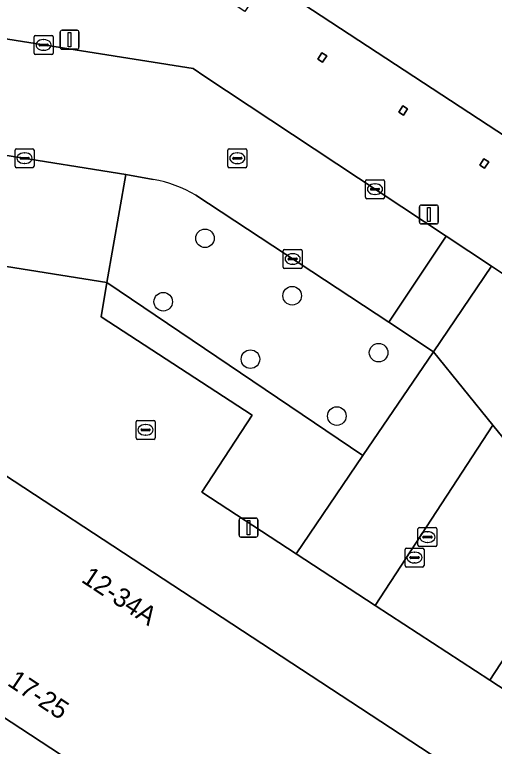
# Model space of a CAD drawing. Extents: x 159279 to 160377, y 384531 to 385888.
# Drawn here: x 159737.29 to 159762.57, y 385027.61 to 385066.14 of the extents above; entities that cross this region are included whole.
import ezdxf

# ---------------------------------------------------------------- set-up
doc = ezdxf.new("R2010")
doc.units = 0
for name, color, linetype in [('IMGEO_Boom', 7, 'Continuous'), ('IMGEO_Groenvoorziening', 7, 'Continuous'), ('IMGEO_Kolk', 7, 'Continuous'), ('IMGEO_Lichtmast', 7, 'Continuous'), ('IMGEO_Pand', 7, 'Continuous'), ('IMGEO_Pand_nummerreeks', 7, 'Continuous'), ('IMGEO_Parkeervlak_open', 7, 'Continuous'), ('IMGEO_Rijbaan_lokaal_open', 7, 'Continuous'), ('IMGEO_Rioolput', 7, 'Continuous'), ('IMGEO_Voetpad_open', 7, 'Continuous')]:
    doc.layers.add(name, color=color, linetype=linetype)

msp = doc.modelspace()

# ---------------------------------------------------------------- linework, layer by layer
at = {"layer": 'IMGEO_Boom'}
for centre in [(159747.32, 385054.365), (159751.915, 385051.341), (159745.121, 385051.024), (159756.467, 385048.344), (159749.716, 385048), (159754.268, 385045.003)]:
    msp.add_circle(centre, 0.489, dxfattribs=at)
at = {"layer": 'IMGEO_Groenvoorziening'}
msp.add_lwpolyline([(159744.597, 385057.462), (159743.153, 385057.729), (159742.143, 385052.029), (159755.642, 385042.921), (159759.353, 385048.383), (159757.004, 385049.945), (159746.836, 385056.637)], dxfattribs=at)
msp.add_lwpolyline([(159752.129, 385037.751), (159755.642, 385042.921), (159742.143, 385052.029), (159741.848, 385050.232), (159749.805, 385045.051), (159747.158, 385040.997)], close=True, dxfattribs=at)
msp.add_arc((159743.481, 385050.982), 6.575, 59.3189, 80.2266, dxfattribs=at)
at = {"layer": 'IMGEO_Kolk'}
for p, q in [((159738.319, 385064.12), (159738.319, 385064.972)), ((159738.394, 385065.046), (159739.246, 385065.046)), ((159738.807, 385064.826), (159738.832, 385064.826)), ((159739.32, 385064.972), (159739.32, 385064.12)), ((159738.578, 385064.54), (159738.578, 385064.552)), ((159739.016, 385064.503), (159738.618, 385064.503)), ((159738.621, 385064.589), (159739.019, 385064.589)), ((159739.062, 385064.552), (159739.062, 385064.54)), ((159739.246, 385064.046), (159738.394, 385064.046)), ((159738.83, 385064.266), (159738.805, 385064.266)), ((159737.316, 385058.157), (159737.316, 385059.009)), ((159737.391, 385059.083), (159738.243, 385059.083)), ((159738.317, 385059.009), (159738.317, 385058.157)), ((159737.618, 385058.626), (159738.016, 385058.626)), ((159737.804, 385058.863), (159737.829, 385058.863)), ((159737.575, 385058.577), (159737.575, 385058.589)), ((159738.013, 385058.54), (159737.615, 385058.54)), ((159737.827, 385058.303), (159737.802, 385058.303)), ((159738.059, 385058.589), (159738.059, 385058.577)), ((159738.243, 385058.083), (159737.391, 385058.083)), ((159755.777, 385056.525), (159755.777, 385057.377)), ((159755.852, 385057.451), (159756.704, 385057.451)), ((159756.265, 385057.231), (159756.29, 385057.231)), ((159756.778, 385057.377), (159756.778, 385056.525)), ((159756.036, 385056.945), (159756.036, 385056.957)), ((159756.474, 385056.908), (159756.076, 385056.908)), ((159756.079, 385056.994), (159756.477, 385056.994)), ((159756.52, 385056.957), (159756.52, 385056.945)), ((159756.704, 385056.451), (159755.852, 385056.451)), ((159756.288, 385056.671), (159756.263, 385056.671)), ((159751.439, 385052.85), (159751.439, 385053.702)), ((159751.514, 385053.776), (159752.366, 385053.776)), ((159752.44, 385053.702), (159752.44, 385052.85)), ((159751.698, 385053.27), (159751.698, 385053.282)), ((159752.136, 385053.233), (159751.738, 385053.233)), ((159751.741, 385053.319), (159752.139, 385053.319)), ((159751.927, 385053.556), (159751.952, 385053.556)), ((159752.182, 385053.282), (159752.182, 385053.27)), ((159751.95, 385052.996), (159751.925, 385052.996)), ((159752.366, 385052.776), (159751.514, 385052.776)), ((159743.766, 385044.778), (159744.618, 385044.778)), ((159743.691, 385043.852), (159743.691, 385044.704)), ((159744.179, 385044.558), (159744.204, 385044.558)), ((159744.692, 385044.704), (159744.692, 385043.852)), ((159743.95, 385044.272), (159743.95, 385044.284)), ((159744.388, 385044.235), (159743.99, 385044.235)), ((159743.993, 385044.321), (159744.391, 385044.321)), ((159744.202, 385043.998), (159744.177, 385043.998)), ((159744.434, 385044.284), (159744.434, 385044.272)), ((159744.618, 385043.778), (159743.766, 385043.778)), ((159758.539, 385038.206), (159758.539, 385039.058)), ((159758.614, 385039.132), (159759.466, 385039.132)), ((159759.54, 385039.058), (159759.54, 385038.206)), ((159758.798, 385038.626), (159758.798, 385038.638)), ((159759.236, 385038.589), (159758.838, 385038.589)), ((159758.841, 385038.675), (159759.239, 385038.675)), ((159759.027, 385038.912), (159759.052, 385038.912)), ((159759.282, 385038.638), (159759.282, 385038.626)), ((159759.05, 385038.352), (159759.025, 385038.352)), ((159759.466, 385038.132), (159758.614, 385038.132))]:
    msp.add_line(p, q, dxfattribs=at)
for points in [[(159738.319, 385064.12), (159738.319, 385064.972)], [(159738.394, 385065.046), (159739.246, 385065.046)], [(159739.32, 385064.972), (159739.32, 385064.12)], [(159739.246, 385064.046), (159738.394, 385064.046)], [(159737.316, 385058.157), (159737.316, 385059.009)], [(159737.391, 385059.083), (159738.243, 385059.083)], [(159738.317, 385059.009), (159738.317, 385058.157)], [(159738.243, 385058.083), (159737.391, 385058.083)], [(159755.777, 385056.525), (159755.777, 385057.377)], [(159755.852, 385057.451), (159756.704, 385057.451)], [(159756.778, 385057.377), (159756.778, 385056.525)], [(159756.704, 385056.451), (159755.852, 385056.451)], [(159751.439, 385052.85), (159751.439, 385053.702)], [(159751.514, 385053.776), (159752.366, 385053.776)], [(159752.44, 385053.702), (159752.44, 385052.85)], [(159752.366, 385052.776), (159751.514, 385052.776)], [(159743.766, 385044.778), (159744.618, 385044.778)], [(159743.691, 385043.852), (159743.691, 385044.704)], [(159744.692, 385044.704), (159744.692, 385043.852)], [(159744.618, 385043.778), (159743.766, 385043.778)], [(159758.539, 385038.206), (159758.539, 385039.058)], [(159758.614, 385039.132), (159759.466, 385039.132)], [(159759.54, 385039.058), (159759.54, 385038.206)], [(159759.466, 385038.132), (159758.614, 385038.132)]]:
    msp.add_lwpolyline(points, dxfattribs=at)
for centre, radius, start, end in [((159738.396, 385064.97), 0.0765, 91.552, 178.448), ((159738.396, 385064.97), 0.0765, 91.552, 178.448), ((159739.244, 385064.97), 0.0765, 1.552, 88.448), ((159739.244, 385064.97), 0.0765, 1.552, 88.448), ((159738.618, 385064.549), 0.0403, 85.8775, 175.7526), ((159738.615, 385064.539), 0.0366, 178.938, 274.7102), ((159739.019, 385064.546), 0.043, 264.8664, 352.4533), ((159739.023, 385064.551), 0.0386, 1.7309, 96.639), ((159738.396, 385064.122), 0.0765, 181.552, 268.448), ((159738.396, 385064.122), 0.0765, 181.552, 268.448), ((159739.244, 385064.122), 0.0765, 271.552, 358.448), ((159739.244, 385064.122), 0.0765, 271.552, 358.448), ((159737.393, 385059.007), 0.0765, 91.552, 178.448), ((159737.393, 385059.007), 0.0765, 91.552, 178.448), ((159738.241, 385059.007), 0.0765, 1.552, 88.448), ((159738.241, 385059.007), 0.0765, 1.552, 88.448), ((159737.615, 385058.586), 0.0403, 85.8775, 175.7526), ((159738.02, 385058.588), 0.0386, 1.7309, 96.639), ((159737.612, 385058.576), 0.0366, 178.938, 274.7102), ((159738.016, 385058.583), 0.043, 264.8664, 352.4533), ((159737.393, 385058.159), 0.0765, 181.552, 268.448), ((159737.393, 385058.159), 0.0765, 181.552, 268.448), ((159738.241, 385058.159), 0.0765, 271.552, 358.448), ((159738.241, 385058.159), 0.0765, 271.552, 358.448), ((159755.854, 385057.375), 0.0765, 91.552, 178.448), ((159755.854, 385057.375), 0.0765, 91.552, 178.448), ((159756.702, 385057.375), 0.0765, 1.552, 88.448), ((159756.702, 385057.375), 0.0765, 1.552, 88.448), ((159756.076, 385056.954), 0.0403, 85.8775, 175.7526), ((159756.073, 385056.944), 0.0366, 178.938, 274.7102), ((159756.477, 385056.951), 0.043, 264.8664, 352.4533), ((159756.481, 385056.956), 0.0386, 1.7309, 96.639), ((159755.854, 385056.527), 0.0765, 181.552, 268.448), ((159755.854, 385056.527), 0.0765, 181.552, 268.448), ((159756.702, 385056.527), 0.0765, 271.552, 358.448), ((159756.702, 385056.527), 0.0765, 271.552, 358.448), ((159751.516, 385053.7), 0.0765, 91.552, 178.448), ((159751.516, 385053.7), 0.0765, 91.552, 178.448), ((159752.364, 385053.7), 0.0765, 1.552, 88.448), ((159752.364, 385053.7), 0.0765, 1.552, 88.448), ((159751.738, 385053.279), 0.0403, 85.8775, 175.7526), ((159751.735, 385053.269), 0.0366, 178.938, 274.7102), ((159752.139, 385053.276), 0.043, 264.8664, 352.4533), ((159752.143, 385053.281), 0.0386, 1.7309, 96.639), ((159751.516, 385052.852), 0.0765, 181.552, 268.448), ((159751.516, 385052.852), 0.0765, 181.552, 268.448), ((159752.364, 385052.852), 0.0765, 271.552, 358.448), ((159752.364, 385052.852), 0.0765, 271.552, 358.448), ((159743.768, 385044.702), 0.0765, 91.552, 178.448), ((159743.768, 385044.702), 0.0765, 91.552, 178.448), ((159744.616, 385044.702), 0.0765, 1.552, 88.448), ((159744.616, 385044.702), 0.0765, 1.552, 88.448), ((159743.99, 385044.281), 0.0403, 85.8775, 175.7526), ((159743.987, 385044.271), 0.0366, 178.938, 274.7102), ((159744.391, 385044.278), 0.043, 264.8664, 352.4533), ((159744.395, 385044.283), 0.0386, 1.7309, 96.639), ((159743.768, 385043.854), 0.0765, 181.552, 268.448), ((159743.768, 385043.854), 0.0765, 181.552, 268.448), ((159744.616, 385043.854), 0.0765, 271.552, 358.448), ((159744.616, 385043.854), 0.0765, 271.552, 358.448), ((159758.616, 385039.056), 0.0765, 91.552, 178.448), ((159758.616, 385039.056), 0.0765, 91.552, 178.448), ((159759.464, 385039.056), 0.0765, 1.552, 88.448), ((159759.464, 385039.056), 0.0765, 1.552, 88.448), ((159758.838, 385038.635), 0.0403, 85.8775, 175.7526), ((159758.835, 385038.625), 0.0366, 178.938, 274.7102), ((159759.239, 385038.632), 0.043, 264.8664, 352.4533), ((159759.243, 385038.637), 0.0386, 1.7309, 96.639), ((159758.616, 385038.208), 0.0765, 181.552, 268.448), ((159758.616, 385038.208), 0.0765, 181.552, 268.448), ((159759.464, 385038.208), 0.0765, 271.552, 358.448), ((159759.464, 385038.208), 0.0765, 271.552, 358.448)]:
    msp.add_arc(centre, radius, start, end, dxfattribs=at)
for centre, major_axis, ratio, start_param, end_param in [((159738.806, 385064.546), (-0.387, 0.002), 0.722429, 4.712389, 7.853982), ((159738.831, 385064.546), (-0.39, 0.002), 0.717154, 1.570796, 4.712389), ((159737.803, 385058.583), (-0.387, 0.002), 0.722429, 4.712389, 7.853982), ((159737.828, 385058.583), (-0.39, 0.002), 0.717154, 1.570796, 4.712389), ((159756.264, 385056.951), (-0.387, 0.002), 0.722429, 4.712389, 7.853982), ((159756.289, 385056.951), (-0.39, 0.002), 0.717154, 1.570796, 4.712389), ((159751.926, 385053.276), (-0.387, 0.002), 0.722429, 4.712389, 7.853982), ((159751.951, 385053.276), (-0.39, 0.002), 0.717154, 1.570796, 4.712389), ((159744.178, 385044.278), (-0.387, 0.002), 0.722429, 4.712389, 7.853982), ((159744.203, 385044.278), (-0.39, 0.002), 0.717154, 1.570796, 4.712389), ((159759.026, 385038.632), (-0.387, 0.002), 0.722429, 4.712389, 7.853982), ((159759.051, 385038.632), (-0.39, 0.002), 0.717154, 1.570796, 4.712389)]:
    msp.add_ellipse(centre, major_axis=major_axis, ratio=ratio, start_param=start_param, end_param=end_param, dxfattribs=at)
at = {"layer": 'IMGEO_Lichtmast'}
for p, q in [((159739.689, 385064.422), (159739.689, 385065.222)), ((159739.689, 385065.222), (159739.689, 385064.422)), ((159739.789, 385065.322), (159740.579, 385065.322)), ((159740.579, 385065.322), (159739.789, 385065.322)), ((159740.679, 385065.222), (159740.679, 385064.422)), ((159740.679, 385064.422), (159740.679, 385065.222)), ((159740.579, 385064.322), (159739.789, 385064.322)), ((159739.789, 385064.322), (159740.579, 385064.322)), ((159758.621, 385055.218), (159758.621, 385056.018)), ((159758.621, 385056.018), (159758.621, 385055.218)), ((159758.721, 385056.118), (159759.511, 385056.118)), ((159759.511, 385056.118), (159758.721, 385056.118)), ((159759.611, 385056.018), (159759.611, 385055.218)), ((159759.611, 385055.218), (159759.611, 385056.018)), ((159759.511, 385055.118), (159758.721, 385055.118)), ((159758.721, 385055.118), (159759.511, 385055.118)), ((159749.118, 385038.73), (159749.118, 385039.53)), ((159749.118, 385039.53), (159749.118, 385038.73)), ((159749.218, 385039.63), (159750.008, 385039.63)), ((159750.008, 385039.63), (159749.218, 385039.63)), ((159750.108, 385039.53), (159750.108, 385038.73)), ((159750.108, 385038.73), (159750.108, 385039.53)), ((159750.008, 385038.63), (159749.218, 385038.63)), ((159749.218, 385038.63), (159750.008, 385038.63))]:
    msp.add_line(p, q, dxfattribs=at)
for points in [[(159740.109, 385065.197), (159740.259, 385065.197), (159740.259, 385064.447), (159740.109, 385064.447), (159740.109, 385065.197)], [(159759.041, 385055.993), (159759.191, 385055.993), (159759.191, 385055.243), (159759.041, 385055.243), (159759.041, 385055.993)], [(159749.538, 385039.505), (159749.688, 385039.505), (159749.688, 385038.755), (159749.538, 385038.755), (159749.538, 385039.505)]]:
    msp.add_lwpolyline(points, dxfattribs=at)
for centre, start, end in [((159739.789, 385065.222), 90, 180), ((159739.789, 385065.222), 90, 180), ((159740.579, 385065.222), 0, 90), ((159740.579, 385065.222), 360, 90), ((159739.789, 385064.422), 180, 270), ((159739.789, 385064.422), 180, 270), ((159740.579, 385064.422), 270, 0), ((159740.579, 385064.422), 270, 0), ((159758.721, 385056.018), 90, 180), ((159758.721, 385056.018), 90, 180), ((159759.511, 385056.018), 0, 90), ((159759.511, 385056.018), 360, 90), ((159758.721, 385055.218), 180, 270), ((159758.721, 385055.218), 180, 270), ((159759.511, 385055.218), 270, 0), ((159759.511, 385055.218), 270, 0), ((159749.218, 385039.53), 90, 180), ((159749.218, 385039.53), 90, 180), ((159750.008, 385039.53), 0, 90), ((159750.008, 385039.53), 360, 90), ((159749.218, 385038.73), 180, 270), ((159749.218, 385038.73), 180, 270), ((159750.008, 385038.73), 270, 0), ((159750.008, 385038.73), 270, 0)]:
    msp.add_arc(centre, 0.1, start, end, dxfattribs=at)
at = {"layer": 'IMGEO_Pand'}
msp.add_lwpolyline([(159750.544, 385067.986), (159788.477, 385043.151), (159787.407, 385041.476), (159787.659, 385041.318), (159787.771, 385041.458), (159791.768, 385038.831), (159791.671, 385038.674), (159791.929, 385038.51), (159792.034, 385038.657), (159796.03, 385036.039), (159795.935, 385035.883), (159796.19, 385035.718), (159796.297, 385035.864), (159800.297, 385033.255), (159800.206, 385033.097), (159800.462, 385032.931), (159800.57, 385033.081), (159804.555, 385030.458)], dxfattribs=at)
for points in [[(159753.484, 385064.132), (159753.265, 385063.797), (159753.519, 385063.631), (159753.738, 385063.966)], [(159757.742, 385061.347), (159757.53, 385061.01), (159757.776, 385060.847), (159757.996, 385061.181)], [(159762.02, 385058.55), (159761.795, 385058.22), (159762.055, 385058.05), (159762.274, 385058.384)], [(159721.603, 385051.823), (159715.693, 385042.917), (159752.249, 385018.976), (159756.551, 385025.584), (159756.906, 385026.112), (159757.162, 385026.161), (159758.452, 385026.409), (159758.603, 385026.313), (159759.18, 385027.212)]]:
    msp.add_lwpolyline(points, close=True, dxfattribs=at)
at = {"layer": 'IMGEO_Parkeervlak_open'}
for points in [[(159742.143, 385052.029), (159743.153, 385057.729), (159730.379, 385059.769), (159730.125, 385059.81), (159729.14, 385054.102)], [(159762.49, 385044.521), (159759.353, 385048.383), (159755.642, 385042.921), (159752.129, 385037.751), (159756.293, 385035.031)], [(159772.362, 385032.302), (159771.983, 385032.834), (159767.259, 385038.65), (159762.324, 385031.093), (159767.138, 385027.949), (159769.593, 385031.74), (159770.679, 385033.418), (159771.795, 385032.678)]]:
    msp.add_lwpolyline(points, close=True, dxfattribs=at)
at = {"layer": 'IMGEO_Rijbaan_lokaal_open'}
for points in [[(159746.836, 385056.637), (159757.004, 385049.945), (159760.028, 385054.47), (159747.307, 385062.891), (159746.691, 385063.299), (159733.14, 385065.444), (159731.323, 385065.732), (159730.379, 385059.769), (159743.153, 385057.729), (159744.597, 385057.462)], [(159754.613, 385010.853), (159757.626, 385015.454), (159759.049, 385017.627), (159762.3, 385022.59), (159761.984, 385024.095), (159761.812, 385024.207), (159762.408, 385025.116), (159759.18, 385027.212), (159758.603, 385026.313), (159758.452, 385026.409), (159757.162, 385026.161), (159756.906, 385026.112), (159756.551, 385025.584), (159752.249, 385018.976), (159715.693, 385042.917)]]:
    msp.add_lwpolyline(points, dxfattribs=at)
for points in [[(159760.028, 385054.47), (159757.004, 385049.945), (159759.353, 385048.383), (159762.407, 385052.895)], [(159768.959, 385045.245), (159768.003, 385046.438), (159764.967, 385050.229), (159763.312, 385052.296), (159762.407, 385052.895), (159759.353, 385048.383), (159762.49, 385044.521), (159767.259, 385038.65), (159771.983, 385032.834), (159772.362, 385032.302), (159776.906, 385035.721), (159776.519, 385035.899), (159776.359, 385036.004), (159771.997, 385041.451)], [(159767.259, 385038.65), (159762.49, 385044.521), (159756.293, 385035.031), (159762.324, 385031.093)]]:
    msp.add_lwpolyline(points, close=True, dxfattribs=at)
msp.add_arc((159743.481, 385050.982), 6.575, 59.3189, 80.2266, dxfattribs=at)
at = {"layer": 'IMGEO_Rioolput'}
for p, q in [((159748.525, 385058.155), (159748.525, 385059.007)), ((159748.6, 385059.081), (159749.452, 385059.081)), ((159749.526, 385059.007), (159749.526, 385058.155)), ((159748.827, 385058.624), (159749.225, 385058.624)), ((159749.013, 385058.861), (159749.038, 385058.861)), ((159748.784, 385058.575), (159748.784, 385058.587)), ((159749.222, 385058.538), (159748.824, 385058.538)), ((159749.036, 385058.301), (159749.011, 385058.301)), ((159749.268, 385058.587), (159749.268, 385058.575)), ((159749.452, 385058.081), (159748.6, 385058.081)), ((159757.86, 385037.128), (159757.86, 385037.98)), ((159757.935, 385038.054), (159758.787, 385038.054)), ((159758.348, 385037.834), (159758.373, 385037.834)), ((159758.861, 385037.98), (159758.861, 385037.128)), ((159758.119, 385037.548), (159758.119, 385037.56)), ((159758.557, 385037.511), (159758.159, 385037.511)), ((159758.162, 385037.597), (159758.56, 385037.597)), ((159758.603, 385037.56), (159758.603, 385037.548)), ((159758.787, 385037.054), (159757.935, 385037.054)), ((159758.371, 385037.274), (159758.346, 385037.274))]:
    msp.add_line(p, q, dxfattribs=at)
for points in [[(159748.525, 385058.155), (159748.525, 385059.007)], [(159748.6, 385059.081), (159749.452, 385059.081)], [(159749.526, 385059.007), (159749.526, 385058.155)], [(159749.452, 385058.081), (159748.6, 385058.081)], [(159757.86, 385037.128), (159757.86, 385037.98)], [(159757.935, 385038.054), (159758.787, 385038.054)], [(159758.861, 385037.98), (159758.861, 385037.128)], [(159758.787, 385037.054), (159757.935, 385037.054)]]:
    msp.add_lwpolyline(points, dxfattribs=at)
for centre, radius, start, end in [((159748.602, 385059.005), 0.0765, 91.552, 178.448), ((159748.602, 385059.005), 0.0765, 91.552, 178.448), ((159749.45, 385059.005), 0.0765, 1.552, 88.448), ((159749.45, 385059.005), 0.0765, 1.552, 88.448), ((159748.824, 385058.584), 0.0403, 85.8775, 175.7526), ((159749.229, 385058.586), 0.0386, 1.7309, 96.639), ((159748.821, 385058.574), 0.0366, 178.938, 274.7102), ((159749.225, 385058.581), 0.043, 264.8664, 352.4533), ((159748.602, 385058.157), 0.0765, 181.552, 268.448), ((159748.602, 385058.157), 0.0765, 181.552, 268.448), ((159749.45, 385058.157), 0.0765, 271.552, 358.448), ((159749.45, 385058.157), 0.0765, 271.552, 358.448), ((159757.937, 385037.978), 0.0765, 91.552, 178.448), ((159757.937, 385037.978), 0.0765, 91.552, 178.448), ((159758.785, 385037.978), 0.0765, 1.552, 88.448), ((159758.785, 385037.978), 0.0765, 1.552, 88.448), ((159758.159, 385037.557), 0.0403, 85.8775, 175.7526), ((159758.156, 385037.547), 0.0366, 178.938, 274.7102), ((159758.56, 385037.554), 0.043, 264.8664, 352.4533), ((159758.564, 385037.559), 0.0386, 1.7309, 96.639), ((159757.937, 385037.13), 0.0765, 181.552, 268.448), ((159757.937, 385037.13), 0.0765, 181.552, 268.448), ((159758.785, 385037.13), 0.0765, 271.552, 358.448), ((159758.785, 385037.13), 0.0765, 271.552, 358.448)]:
    msp.add_arc(centre, radius, start, end, dxfattribs=at)
for centre, major_axis, ratio, start_param, end_param in [((159749.012, 385058.581), (-0.387, 0.002), 0.722429, 4.712389, 7.853982), ((159749.037, 385058.581), (-0.39, 0.002), 0.717154, 1.570796, 4.712389), ((159758.347, 385037.554), (-0.387, 0.002), 0.722429, 4.712389, 7.853982), ((159758.372, 385037.554), (-0.39, 0.002), 0.717154, 1.570796, 4.712389)]:
    msp.add_ellipse(centre, major_axis=major_axis, ratio=ratio, start_param=start_param, end_param=end_param, dxfattribs=at)
at = {"layer": 'IMGEO_Voetpad_open'}
for points in [[(159804.555, 385030.458), (159800.57, 385033.081), (159800.462, 385032.931), (159800.206, 385033.097), (159800.297, 385033.255), (159796.297, 385035.864), (159796.19, 385035.718), (159795.935, 385035.883), (159796.03, 385036.039), (159792.034, 385038.657), (159791.929, 385038.51), (159791.671, 385038.674), (159791.768, 385038.831), (159787.771, 385041.458), (159787.659, 385041.318), (159787.407, 385041.476), (159788.477, 385043.151), (159750.544, 385067.986), (159749.427, 385066.306), (159744.541, 385069.513), (159726.143, 385081.628)], [(159730.125, 385059.81), (159727.505, 385060.228), (159716.203, 385062.033), (159712.839, 385064.165), (159711.142, 385065.24), (159708.7, 385066.788), (159705.963, 385068.522), (159705.83, 385068.32), (159703.099, 385064.194), (159696.145, 385068.756), (159693.731, 385070.357), (159689.069, 385073.382), (159686.763, 385074.878), (159688.108, 385070.646), (159712.21, 385054.869), (159713.626, 385057.048), (159721.603, 385051.823), (159759.18, 385027.212), (159762.408, 385025.116), (159794.238, 385004.267), (159797.331, 385002.832)], [(159733.14, 385065.444), (159746.691, 385063.299), (159747.307, 385062.891), (159760.028, 385054.47), (159762.407, 385052.895), (159763.312, 385052.296)], [(159780.636, 385026.908), (159772.362, 385032.302), (159771.795, 385032.678), (159770.679, 385033.418), (159769.593, 385031.74), (159767.138, 385027.949), (159762.324, 385031.093), (159756.293, 385035.031), (159752.129, 385037.751), (159747.158, 385040.997), (159749.805, 385045.051), (159741.848, 385050.232), (159742.143, 385052.029), (159729.14, 385054.102), (159730.125, 385059.81)]]:
    msp.add_lwpolyline(points, dxfattribs=at)
for points in [[(159753.484, 385064.132), (159753.738, 385063.966), (159753.519, 385063.631), (159753.265, 385063.797)], [(159757.742, 385061.347), (159757.996, 385061.181), (159757.776, 385060.847), (159757.53, 385061.01)], [(159762.02, 385058.55), (159762.274, 385058.384), (159762.055, 385058.05), (159761.795, 385058.22)]]:
    msp.add_lwpolyline(points, close=True, dxfattribs=at)

# ---------------------------------------------------------------- texts
at = {"layer": 'IMGEO_Pand_nummerreeks'}
for s, p in [('12-34A', (159740.752, 385036.304)), ('17-25', (159736.856, 385030.86))]:
    msp.add_text(s, height=1, rotation=326.5794, dxfattribs=at).set_placement(p)

doc.saveas('drawing.dxf')
